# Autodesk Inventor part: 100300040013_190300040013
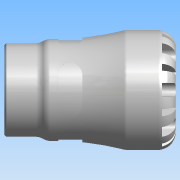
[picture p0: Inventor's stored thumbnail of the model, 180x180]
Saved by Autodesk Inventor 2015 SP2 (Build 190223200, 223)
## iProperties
Created: 2016-12
Part Number: 100300040013_190300040013
Material: PVC-Piping
Description: PLASSON FEMALE ADAPTOR 40X1.1/4" SERIES 1
Document SubType Name: Modeling
Designer: KIM
Mass: 664.223 g
Surface Area: 733.008 cm^2
Volume: 474.445 cm^3
Density: 1.4 g/cm^3
Appearance: Smooth - White
Author: KIM
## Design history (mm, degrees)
derived "1003.ipt"
feature "Solid1::1003.ipt"
tag "TaggingFeature1"
body "Solid1"
other parameters: "d1" = 29.4, "d8" = 59.5, "d13" = 8, "d14" = 8, "d15" = 0, "d17" = 360 deg, "d19" = 8 deg, "d20" = 0.8, "d21" = 0.8, "d22" = 8 deg, "d24" = 0, "d26" = 360 deg, "d32" = 7, "d33" = 7, "d39" = 1.16856, "d42" = 38.952, "d43" = 54.6, "d46" = 3.33333, "d47" = 24, "d48" = 37.0044, "d50" = 1.98, "d51" = 0.7, "d54" = 14, "d55" = 8.8, "d57" = 15.68, "d58" = 0, "d68" = 360 deg, "d72" = 0.8, "d74" = 0, "d76" = 11.9, "Rp" = 38.952, "l_2" = 24, "d9" = 10, "d49" = 6
